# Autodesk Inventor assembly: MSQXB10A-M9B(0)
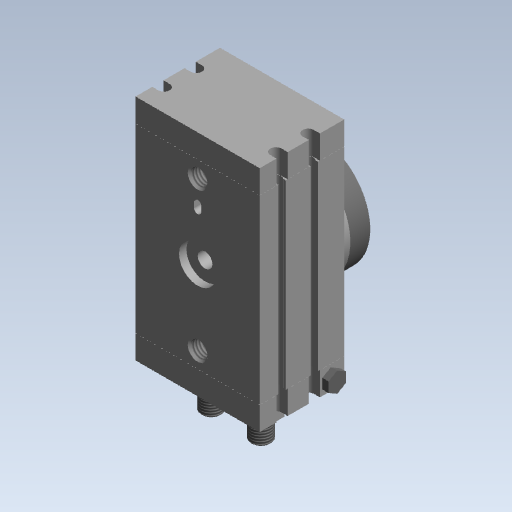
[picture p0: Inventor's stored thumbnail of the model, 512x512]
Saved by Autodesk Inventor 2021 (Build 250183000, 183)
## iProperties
Category: PARTsolutions
Part Number: MSQXB10A-M9B(0)
Catalog Web Link: www.cadenas.de
Description: MSQX-Low-Speed Rotary Table Rack & Pinion Style
Document SubType Name: Assembly
Designer: partserver
Mass: 168.018 g
Surface Area: 337.625 cm^2
Volume: 168.018 cm^3
Density: 1 g/cm^3
PSOL_IDENT_0: {$CADENAS_DATA\23d-libs\smc_jp\actuator\rotary_actuator\msqx\msqx_asmtab.prj},218 {VTYP=3D},{STYP=AS
PSOL_IDENT_1: STAB},{NB=MSQXB10A-M9B(0)},{LINA=MSQXB10A-M9B},{NN=MSQX},{DATE=09.12.2020 02:49:37},{GEOMDATE=09.03.
PSOL_IDENT_2: 2020 10:24:15},{VERSION=},{LINEID=160},{WBVAR=THREAD1,AUTOSW,LEAD,NUMBER,OMSC,THREAD},{WBNUMERIC=}
PSOL_IDENT_3: {NB=MSQXB10A-M9B(0)},{LINA=MSQXB10A-M9B},{KT=DUMMY},{ORDER=MSQXB10A-M9B},{SIZE=10},{THREAD1=},{AUTOS
PSOL_IDENT_4: W=-M9B},{LEAD=},{LEADX= '','(-) 0.5 m' , 'M','(M) 1 m' , 'L','(L) 3 m' , 'Z','(Z) 5 m' },{NUMBER=},{
PSOL_IDENT_5: SWSIGNX= '','(-) 2 pcs' , 'S','(S) 1 pc' },{PORTX= '', '(-) M5' },{OMSC=},{THREAD=0},{NENN=MSQXB10},
PSOL_IDENT_6: {MODEL=MSQXB10A-M9B},{X=},{TIF=1},{AA=55.4},{A=50},{AU=8.6},{AV=20.0},{AW=15.5},{AX=12},{AY=4},{BA=9
PSOL_IDENT_7: .5},{BB=34.5},{BC=27.8},{BD=60},{BE=27},{CA=4.5},{CB=28.5},{D=45h9},{D1=45},{DD=46h9},{DD1=46},{DE=2
PSOL_IDENT_8: 0H9},{DE1=20},{DF=6},{DG=15H9},{DG1=15},{FA=8.0},{FB=4.0},{FC=3.0},{FD=4.5},{H=13},{J=6.8},{JA=11.0}
PSOL_IDENT_9: ,{JB=6.5},{JC=M8x1.25},{JC1=8},{JCP=1.25},{JD=12},{JJ=M5x0.8},{JJ1=5},{JJP=0.80},{JU=M8x1},{JU1=8},{
PSOL_IDENT_10: JUP=1.0},{P=M5x0.8},{P1=5.000},{PP=0.8},{Q=34},{S=92},{SD=9.0},{SE=13},{SF=45},{SU=17.7},{UU=47},{WA=
PSOL_IDENT_11: 15.0},{WB=3H9},{WB1=3},{WC=3.5},{WD=M5x0.8},{WD1=5},{WDP=0.80},{WE=8.0},{WF=32},{XA=27},{XB=3H9},{XB
PSOL_IDENT_12: 1=3},{XC=3.5},{YA=19},{YB=3H9},{YB1=3},{YC=3.5},{F1=6.917},{F2=5},{Y1=8},{Y2=12},{H1=5.000},{H2=5.00
PSOL_IDENT_13: 0},{SWA=61},{SWB=43},{PD=0.3},{EA=47.1},{EB=44.3},{EC=33.5},{ED=14.0},{EE=91.4},{EF=80},{GA=20},{GB=
PSOL_IDENT_14: 15.6},{GC=11},{GD=7.5},{GE=45.2},{K=M8x1},{NA=10.0},{MB=5.5},{NC=12.5},{ND=4},{PPATH=assembly/msqx_a
PSOL_IDENT_15: smsbl.prj}
NB: MSQXB10A-M9B(0)
NN: MSQX
NT: Low-Speed Rotary Table Rack & Pinion Style
NBSYN: $ORDER.($THREAD.)
LINA: MSQXB10A-M9B
CATALOG: SMC (JP
ROWDESC: MSQXB10
SIZE: 10
THREAD1: (-) M5
AUTOSW: M9B Solid state-General-Grommet-Indicator light:Yes-2 wire-In line
LEAD: (-) 0.5 m
NUMBER: (-) 2 pcs
OMSC: (-) Without order
THREAD: on
ARTICLENO: MSQXB10A-M9B(0)
BOMINFO: MSQXB10A-M9B
CREATOR: CADENAS GmbH
Title: MSQXB10A-M9B
Author: Cadenas PARTsolutions
Comments: Low-Speed Rotary Table Rack & Pinion Style
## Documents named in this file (5)
- D:\01 Paralaia\Grupos de Traballo\GT Maquetas\CAD 3D\E_Medida\SMC_JP_MSQXB10AM9B0\MSQXB10A-M9B(0).iam
- D:\01 Paralaia\Grupos de Traballo\GT Maquetas\CAD 3D\E_Medida\SMC_JP_MSQXB10AM9B0\MSQX10(0)_BODY.ipt
- D:\01 Paralaia\Grupos de Traballo\GT Maquetas\CAD 3D\E_Medida\SMC_JP_MSQXB10AM9B0\MSQX10(0)_Table.ipt
- D:\01 Paralaia\Grupos de Traballo\GT Maquetas\CAD 3D\E_Medida\SMC_JP_MSQXB10AM9B0\MSQX_M-5P.ipt
- D:\01 Paralaia\Grupos de Traballo\GT Maquetas\CAD 3D\E_Medida\SMC_JP_MSQXB10AM9B0\D-M9B_MSQX.ipt
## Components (6 placed, 4 different names)
1. MSQX10(0)_BODY:1
2. MSQX10(0)_Table:1 — Insertar:1
3. MSQX_M-5P:1
4. MSQX_M-5P:2
5. D-M9B_MSQX:1
6. D-M9B_MSQX:2
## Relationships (1: Insert 1)
- Insertar:1: MSQX10(0)_Table:1
